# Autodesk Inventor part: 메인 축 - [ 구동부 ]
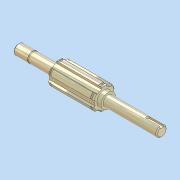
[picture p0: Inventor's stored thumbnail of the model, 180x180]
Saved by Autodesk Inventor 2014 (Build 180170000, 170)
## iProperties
Created: 2012-05
Part Number: 메인 축 - [ 구동부 ]
Document SubType Name: 모델링
Designer: SeoGD™
Mass: 168.566 g
Surface Area: 72.5104 cm^2
Volume: 21.4461 cm^3
Density: 7.86 g/cm^3
Material: 강철, 연강
Appearance: 강철
변환 표준: STEP AP214IS
파일 이름: C:\Users\SeoGD\Desktop\?쒗뿕\硫붿씤 異?.stp
전처리기: Build: 253, Release: 2010 SP1 - Date: Wed 07/29/2009
전송 단위: 밀리미터
불확실성: 0.01
Author: SeoGD™
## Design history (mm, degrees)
sketch "스케치1"
  geometry: L1 (-69.5, 0)-(69.5, 0); L2 (69.5, 0)-(69.5, 5); L3 (69.5, 5)-(55.5, 5); L4 (55.5, 5)-(55.5, 4.8); L5 (55.5, 4.8)-(54.35, 4.8); L6 (54.35, 4.8)-(54.35, 5); L7 (54.35, 5)-(30.5, 5); L8 (30.5, 5)-(30.5, 9); L9 (30.5, 9)-(-13.5, 9); L10 (-13.5, 9)-(-13.5, 7); L11 (-13.5, 7)-(-17.5, 7); L12 (-17.5, 7)-(-17.5, 5); L13 (-17.5, 5)-(-69.5, 5); L14 (-69.5, 5)-(-69.5, 0); 2 further points
  constraints: 28 end point, 9 parallel, 4 collinear, 2 perpendicular, 1 coincident, 1 horizontal, 1 midpoint
  dimensions: "d2" = 1.15 distance between parallel lines of L6 L4; "d3" = 10 diameter of L3 L1; "d4" = 9.6 diameter of L5 L1; "d6" = 44 distance between parallel lines of L10 L8; "d7" = 4 distance between parallel lines of L12 L10; "d8" = 14 diameter of L11 L1; "d9" = 18 diameter of L9 L1; "d33" = 52 distance from line of L12.end L14; "d37" = 39 distance between parallel lines of L8 L2; "d38" = 14 distance between parallel lines of L2 L4
revolve "회전1" sketch "스케치1" stored, may be unused: angle "d10" = 90 deg
sketch "스케치2"
  geometry: L1 (2.5, 10.712)-(2.5, 8.646); L2 (-2.5, 10.712)-(-2.5, 8.646); A1 r 9 centre (0, 0) between (2.5, 8.646) and (-2.5, 8.646) reference; A2 r 11 centre (0, 0) between (2.5, 10.712) and (-2.5, 10.712); 1 further point
  constraints: 4 end point, 4 point on circle, 2 parallel, 1 centre point, 1 coincident, 1 vertical
  dimensions: "d11" = 22 diameter of A2; "d12" = 5 distance between parallel lines of L1 L2
extrude "돌출1" join sketch "스케치2" stored distance "d13" = 10; taper "d14" = 0 deg
chamfer "모따기1" distance "d15" = 1; stored, may be unused: second distance "d16" = 2, angle "d17" = 45 deg
node "작업 평면1"
node "작업 평면2"
sketch "스케치3"
  geometry: L1 (2.5, 10.712)-(2.5, 10.198); L2 (-2.5, 10.712)-(-2.5, 10.198); A1 r 11 centre (0, 0) between (2.5, 10.712) and (-2.5, 10.712) reference; A2 r 10.5 centre (0, 0) between (2.5, 10.198) and (-2.5, 10.198); 1 further point
  constraints: 4 end point, 2 point on circle, 1 centre point, 1 coincident, 1 parallel, 1 vertical
  dimensions: "d19" = 21 diameter of A2
extrude "돌출2" cut sketch "스케치3" distance "d20" = 1.35; taper "d21" = 0 deg
node "작업 평면3"
sketch "스케치4"
  geometry: L1 (-26, -5)-(-26, 5) reference; L2 (-26, 1.5)-(-12.5, 1.5); L3 (-12.5, -1.5)-(-26, -1.5); A1 r 1.5 centre (-12.5, 0) between (-12.5, -1.5) and (-12.5, 1.5); 2 further points
  constraints: 4 end point, 2 perpendicular, 2 point on circle, 2 point on line, 2 tangent, 1 centre point, 1 horizontal alignment, 1 midpoint
  dimensions: "d25" = 3 distance between parallel lines of L3 L2; "d26" = 15 dimension on A1 L1
extrude "돌출3" cut sketch "스케치4" distance "d27" = 1.8; taper "d28" = 0 deg
chamfer "모따기2" distance "d29" = 1; stored, may be unused: second distance "d30" = 2, angle "d31" = 45 deg
node "솔리드1"
node "솔리드 본체"
node "곡면 본체"
mirror "대칭1"
pattern_circular "원형 패턴1" dims "d23" = 360 deg
node "솔리드2"
other parameters: "d18" = -1.65
